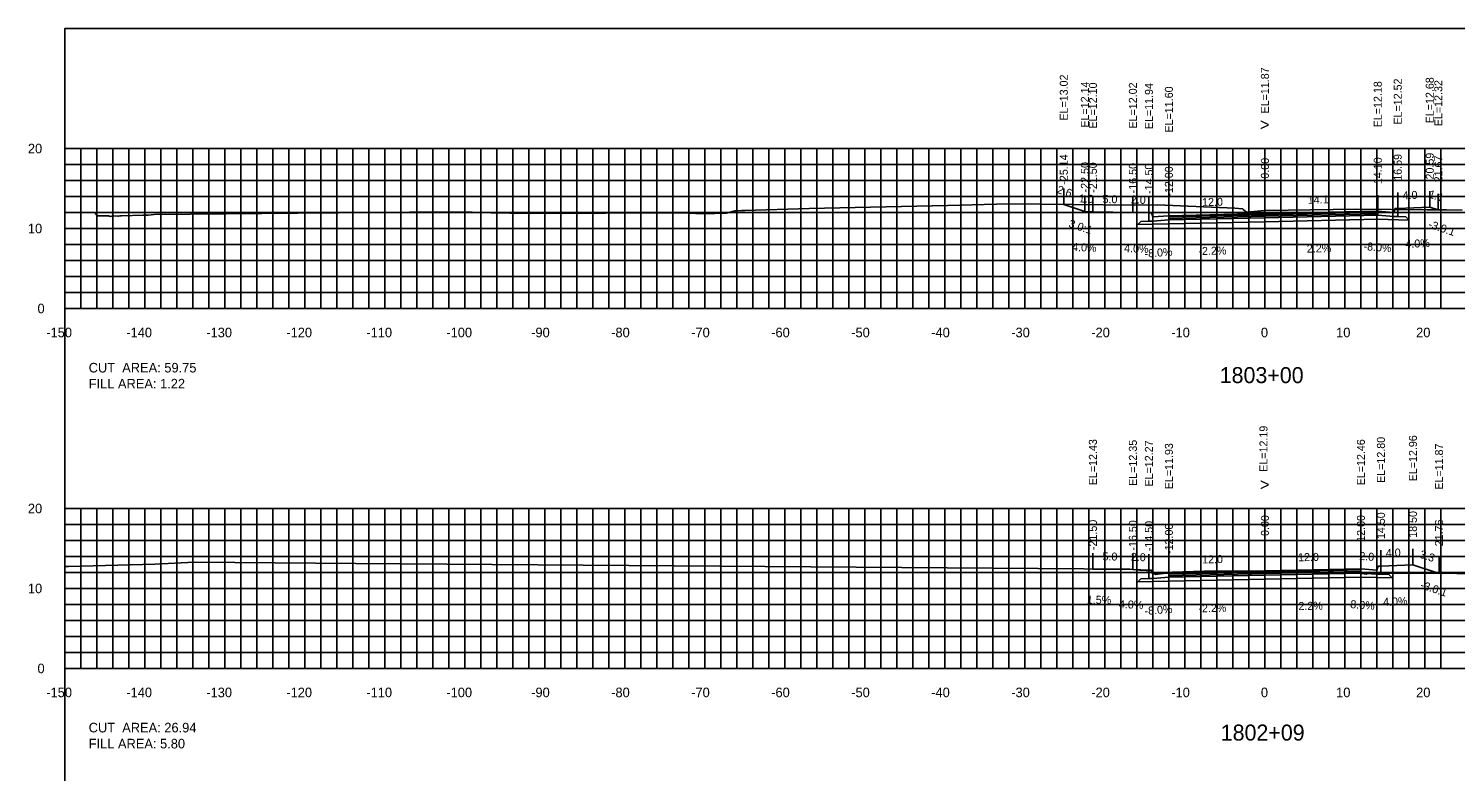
# Model space of a CAD drawing. Extents: x 1797759 to 1802785, y 249826 to 250371.
# Drawn here: x 1802136.5 to 1802314.8, y 250176.5 to 250269.4 of the extents above; entities that cross this region are included whole.
import ezdxf

# ---------------------------------------------------------------- set-up
doc = ezdxf.new("R2010")
doc.units = 0
for name, color, linetype in [('29', 7, 'Continuous'), ('AXIS', 7, 'Continuous'), ('great seal', 7, 'Continuous'), ('Level 1', 7, 'Continuous'), ('Level 10', 7, 'Continuous'), ('Level 13', 7, 'Continuous'), ('Level 15', 7, 'Continuous'), ('Level 30', 7, 'Continuous'), ('Level 40', 7, 'Continuous'), ('Level 45', 7, 'Continuous'), ('Level 63', 7, 'Continuous'), ('Level 7', 7, 'Continuous'), ('LS-SURVEY POINT', 7, 'Continuous'), ('PIPE', 7, 'Continuous'), ('TOPO', 7, 'Continuous')]:
    doc.layers.add(name, color=color, linetype=linetype)

msp = doc.modelspace()

# ---------------------------------------------------------------- linework, layer by layer
at = {"layer": '29'}
for points in [[(1802279, 250245.88), (1802291, 250246.15), (1802305.1, 250246.46), (1802305.1, 250246.27), (1802291, 250245.96), (1802279, 250245.69)], [(1802279, 250201.21), (1802291, 250201.48), (1802303, 250201.74), (1802303, 250201.55), (1802291, 250201.29), (1802279, 250201.02)]]:
    msp.add_lwpolyline(points, close=True, dxfattribs=at)
at = {"layer": 'AXIS'}
for p, q in [((1802265.86, 250247.45), (1802265.86, 250249.45)), ((1802268.5, 250246.57), (1802268.5, 250248.57)), ((1802269.5, 250246.53), (1802269.5, 250248.53)), ((1802274.5, 250246.45), (1802274.5, 250248.45)), ((1802276.5, 250246.37), (1802276.5, 250248.37)), ((1802279, 250246.03), (1802279, 250248.03)), ((1802291, 250246.3), (1802291, 250248.3)), ((1802305.1, 250246.61), (1802305.1, 250248.61)), ((1802307.6, 250246.95), (1802307.6, 250248.95)), ((1802311.6, 250247.11), (1802311.6, 250249.11)), ((1802312.67, 250246.75), (1802312.67, 250248.75)), ((1802269.5, 250201.86), (1802269.5, 250203.86)), ((1802274.5, 250201.78), (1802274.5, 250203.78)), ((1802276.5, 250201.7), (1802276.5, 250203.7)), ((1802279, 250201.36), (1802279, 250203.36)), ((1802291, 250201.63), (1802291, 250203.63)), ((1802303, 250201.89), (1802303, 250203.89)), ((1802305.5, 250202.23), (1802305.5, 250204.23)), ((1802309.5, 250202.39), (1802309.5, 250204.39)), ((1802312.76, 250201.3), (1802312.76, 250203.3))]:
    msp.add_line(p, q, dxfattribs=at)
for points in [[(1802141, 250079.43), (1802441, 250079.43), (1802441, 250269.43), (1802141, 250269.43)], [(1802279, 250246.03), (1802277, 250245.87), (1802276.83, 250246.37), (1802276.5, 250246.37), (1802276.5, 250245.34), (1802277, 250245.34), (1802279, 250245.5)], [(1802305.1, 250246.61), (1802307.1, 250246.45), (1802307.27, 250246.95), (1802307.6, 250246.95), (1802307.6, 250245.92), (1802307.1, 250245.92), (1802305.1, 250246.08)], [(1802279, 250201.36), (1802277, 250201.2), (1802276.83, 250201.7), (1802276.5, 250201.7), (1802276.5, 250200.67), (1802277, 250200.67), (1802279, 250200.83)], [(1802303, 250201.89), (1802305, 250201.73), (1802305.17, 250202.23), (1802305.5, 250202.23), (1802305.5, 250201.2), (1802305, 250201.2), (1802303, 250201.36)]]:
    msp.add_lwpolyline(points, close=True, dxfattribs=at)
at = {"layer": 'great seal'}
for points in [[(1802141, 250246.46), (1802142.96, 250246.44), (1802144.83, 250246.42), (1802144.87, 250246.29), (1802145.01, 250246.1), (1802145.03, 250246.01), (1802145.75, 250246.02), (1802145.86, 250246.02), (1802146.44, 250246.02), (1802146.45, 250246.02), (1802146.48, 250246.02), (1802146.57, 250245.99), (1802146.61, 250245.98), (1802146.73, 250245.95), (1802147, 250246.02), (1802147.02, 250246.02), (1802147.13, 250246.01), (1802147.65, 250245.98), (1802147.72, 250245.99), (1802147.91, 250246.03), (1802148.09, 250246.03), (1802150.82, 250246.08), (1802151.43, 250246.08), (1802152.19, 250246.19), (1802174.65, 250246.39), (1802175.24, 250246.41), (1802184.1, 250246.49), (1802186.87, 250246.47), (1802191.91, 250246.46), (1802191.94, 250246.45), (1802198.98, 250246.29), (1802199.05, 250246.31), (1802218.14, 250246.38), (1802220.77, 250246.28), (1802223.66, 250246.36), (1802224.78, 250246.64), (1802225.62, 250246.67), (1802225.99, 250246.69), (1802234.03, 250246.92), (1802251.33, 250247.32), (1802258.99, 250247.52), (1802274.75, 250247.36), (1802277.54, 250247.39), (1802287.25, 250246.96), (1802288.2, 250246.9), (1802288.3, 250246.79), (1802288.68, 250246.46), (1802289.22, 250246.53), (1802290.9, 250246.68), (1802293.91, 250246.71), (1802302.32, 250246.83), (1802311.28, 250246.75), (1802313.71, 250246.75), (1802315.65, 250246.74)], [(1802141, 250202.16), (1802141.46, 250202.18), (1802152.27, 250202.48), (1802157.21, 250202.7), (1802177.37, 250202.55), (1802274.05, 250201.83), (1802274.1, 250201.83), (1802275.38, 250201.72), (1802276.93, 250201.62), (1802277.09, 250201.44), (1802277.32, 250201.16), (1802278.59, 250201.33), (1802279.41, 250201.45), (1802283.42, 250201.57), (1802290.08, 250201.65), (1802299.57, 250201.38), (1802302.08, 250201.4), (1802302.77, 250201.35), (1802303.71, 250201.23), (1802303.81, 250201.31), (1802304.29, 250201.29), (1802306.24, 250201.28), (1802306.24, 250201.28), (1802307.57, 250201.34), (1802307.6, 250201.33), (1802329.75, 250201.22)]]:
    msp.add_lwpolyline(points, dxfattribs=at)
at = {"layer": 'Level 1'}
for points in [[(1802265.86, 250247.45), (1802268.5, 250246.57), (1802269.5, 250246.53), (1802274.5, 250246.45), (1802276.5, 250246.37), (1802276.83, 250246.37), (1802277, 250245.87), (1802279, 250246.03), (1802291, 250246.3), (1802305.1, 250246.61), (1802307.1, 250246.45), (1802307.27, 250246.95), (1802307.6, 250246.95), (1802311.6, 250247.11), (1802312.67, 250246.75)], [(1802269.5, 250201.86), (1802274.5, 250201.78), (1802276.5, 250201.7), (1802276.83, 250201.7), (1802277, 250201.2), (1802279, 250201.36), (1802291, 250201.63), (1802303, 250201.89), (1802305, 250201.73), (1802305.17, 250202.23), (1802305.5, 250202.23), (1802309.5, 250202.39), (1802312.76, 250201.3)]]:
    msp.add_lwpolyline(points, dxfattribs=at)
at = {"layer": 'Level 13'}
for points in [[(1802305.1, 250245.58), (1802309, 250245.49), (1802308.6, 250245.9), (1802307.6, 250245.92), (1802307.1, 250245.92), (1802305.1, 250246.08), (1802291, 250245.77), (1802279, 250245.5), (1802277, 250245.34), (1802276.5, 250245.34), (1802275.5, 250245.32), (1802275.1, 250244.92), (1802279, 250245), (1802291, 250245.27)], [(1802303, 250200.86), (1802306.9, 250200.77), (1802306.5, 250201.18), (1802305.5, 250201.2), (1802305, 250201.2), (1802303, 250201.36), (1802291, 250201.1), (1802279, 250200.83), (1802277, 250200.67), (1802276.5, 250200.67), (1802275.5, 250200.65), (1802275.1, 250200.25), (1802279, 250200.33), (1802291, 250200.6)]]:
    msp.add_lwpolyline(points, close=True, dxfattribs=at)
at = {"layer": 'Level 15'}
for p, q in [((1802141, 250254.43), (1802441, 250254.43)), ((1802141, 250234.43), (1802141, 250254.43)), ((1802143, 250234.43), (1802143, 250254.43)), ((1802145, 250234.43), (1802145, 250254.43)), ((1802147, 250234.43), (1802147, 250254.43)), ((1802149, 250234.43), (1802149, 250254.43)), ((1802151, 250234.43), (1802151, 250254.43)), ((1802153, 250234.43), (1802153, 250254.43)), ((1802155, 250234.43), (1802155, 250254.43)), ((1802157, 250234.43), (1802157, 250254.43)), ((1802159, 250234.43), (1802159, 250254.43)), ((1802161, 250234.43), (1802161, 250254.43)), ((1802163, 250234.43), (1802163, 250254.43)), ((1802165, 250234.43), (1802165, 250254.43)), ((1802167, 250234.43), (1802167, 250254.43)), ((1802169, 250234.43), (1802169, 250254.43)), ((1802171, 250234.43), (1802171, 250254.43)), ((1802173, 250234.43), (1802173, 250254.43)), ((1802175, 250234.43), (1802175, 250254.43)), ((1802177, 250234.43), (1802177, 250254.43)), ((1802179, 250234.43), (1802179, 250254.43)), ((1802181, 250234.43), (1802181, 250254.43)), ((1802183, 250234.43), (1802183, 250254.43)), ((1802185, 250234.43), (1802185, 250254.43)), ((1802187, 250234.43), (1802187, 250254.43)), ((1802189, 250234.43), (1802189, 250254.43)), ((1802191, 250234.43), (1802191, 250254.43)), ((1802193, 250234.43), (1802193, 250254.43)), ((1802195, 250234.43), (1802195, 250254.43)), ((1802197, 250234.43), (1802197, 250254.43)), ((1802199, 250234.43), (1802199, 250254.43)), ((1802201, 250234.43), (1802201, 250254.43)), ((1802203, 250234.43), (1802203, 250254.43)), ((1802205, 250234.43), (1802205, 250254.43)), ((1802207, 250234.43), (1802207, 250254.43)), ((1802209, 250234.43), (1802209, 250254.43)), ((1802211, 250234.43), (1802211, 250254.43)), ((1802213, 250234.43), (1802213, 250254.43)), ((1802215, 250234.43), (1802215, 250254.43)), ((1802217, 250234.43), (1802217, 250254.43)), ((1802219, 250234.43), (1802219, 250254.43)), ((1802221, 250234.43), (1802221, 250254.43)), ((1802223, 250234.43), (1802223, 250254.43)), ((1802225, 250234.43), (1802225, 250254.43)), ((1802227, 250234.43), (1802227, 250254.43)), ((1802229, 250234.43), (1802229, 250254.43)), ((1802231, 250234.43), (1802231, 250254.43)), ((1802233, 250234.43), (1802233, 250254.43)), ((1802235, 250234.43), (1802235, 250254.43)), ((1802237, 250234.43), (1802237, 250254.43)), ((1802239, 250234.43), (1802239, 250254.43)), ((1802241, 250234.43), (1802241, 250254.43)), ((1802243, 250234.43), (1802243, 250254.43)), ((1802245, 250234.43), (1802245, 250254.43)), ((1802247, 250234.43), (1802247, 250254.43)), ((1802249, 250234.43), (1802249, 250254.43)), ((1802251, 250234.43), (1802251, 250254.43)), ((1802253, 250234.43), (1802253, 250254.43)), ((1802255, 250234.43), (1802255, 250254.43)), ((1802257, 250234.43), (1802257, 250254.43)), ((1802259, 250234.43), (1802259, 250254.43)), ((1802261, 250234.43), (1802261, 250254.43)), ((1802263, 250234.43), (1802263, 250254.43)), ((1802265, 250234.43), (1802265, 250254.43)), ((1802267, 250234.43), (1802267, 250254.43)), ((1802269, 250234.43), (1802269, 250254.43)), ((1802271, 250234.43), (1802271, 250254.43)), ((1802273, 250234.43), (1802273, 250254.43)), ((1802275, 250234.43), (1802275, 250254.43)), ((1802277, 250234.43), (1802277, 250254.43)), ((1802279, 250234.43), (1802279, 250254.43)), ((1802281, 250234.43), (1802281, 250254.43)), ((1802283, 250234.43), (1802283, 250254.43)), ((1802285, 250234.43), (1802285, 250254.43)), ((1802287, 250234.43), (1802287, 250254.43)), ((1802289, 250234.43), (1802289, 250254.43)), ((1802291, 250234.43), (1802291, 250254.43)), ((1802293, 250234.43), (1802293, 250254.43)), ((1802295, 250234.43), (1802295, 250254.43)), ((1802297, 250234.43), (1802297, 250254.43)), ((1802299, 250234.43), (1802299, 250254.43)), ((1802301, 250234.43), (1802301, 250254.43)), ((1802303, 250234.43), (1802303, 250254.43)), ((1802305, 250234.43), (1802305, 250254.43)), ((1802307, 250234.43), (1802307, 250254.43)), ((1802309, 250234.43), (1802309, 250254.43)), ((1802311, 250234.43), (1802311, 250254.43)), ((1802313, 250234.43), (1802313, 250254.43)), ((1802141, 250252.43), (1802441, 250252.43)), ((1802141, 250250.43), (1802441, 250250.43)), ((1802141, 250248.43), (1802441, 250248.43)), ((1802141, 250246.43), (1802441, 250246.43)), ((1802141, 250244.43), (1802441, 250244.43)), ((1802141, 250242.43), (1802441, 250242.43)), ((1802141, 250240.43), (1802441, 250240.43)), ((1802141, 250238.43), (1802441, 250238.43)), ((1802141, 250236.43), (1802441, 250236.43)), ((1802141, 250234.43), (1802441, 250234.43)), ((1802141, 250209.43), (1802441, 250209.43)), ((1802141, 250189.43), (1802141, 250209.43)), ((1802143, 250189.43), (1802143, 250209.43)), ((1802145, 250189.43), (1802145, 250209.43)), ((1802147, 250189.43), (1802147, 250209.43)), ((1802149, 250189.43), (1802149, 250209.43)), ((1802151, 250189.43), (1802151, 250209.43)), ((1802153, 250189.43), (1802153, 250209.43)), ((1802155, 250189.43), (1802155, 250209.43)), ((1802157, 250189.43), (1802157, 250209.43)), ((1802159, 250189.43), (1802159, 250209.43)), ((1802161, 250189.43), (1802161, 250209.43)), ((1802163, 250189.43), (1802163, 250209.43)), ((1802165, 250189.43), (1802165, 250209.43)), ((1802167, 250189.43), (1802167, 250209.43)), ((1802169, 250189.43), (1802169, 250209.43)), ((1802171, 250189.43), (1802171, 250209.43)), ((1802173, 250189.43), (1802173, 250209.43)), ((1802175, 250189.43), (1802175, 250209.43)), ((1802177, 250189.43), (1802177, 250209.43)), ((1802179, 250189.43), (1802179, 250209.43)), ((1802181, 250189.43), (1802181, 250209.43)), ((1802183, 250189.43), (1802183, 250209.43)), ((1802185, 250189.43), (1802185, 250209.43)), ((1802187, 250189.43), (1802187, 250209.43)), ((1802189, 250189.43), (1802189, 250209.43)), ((1802191, 250189.43), (1802191, 250209.43)), ((1802193, 250189.43), (1802193, 250209.43)), ((1802195, 250189.43), (1802195, 250209.43)), ((1802197, 250189.43), (1802197, 250209.43)), ((1802199, 250189.43), (1802199, 250209.43)), ((1802201, 250189.43), (1802201, 250209.43)), ((1802203, 250189.43), (1802203, 250209.43)), ((1802205, 250189.43), (1802205, 250209.43)), ((1802207, 250189.43), (1802207, 250209.43)), ((1802209, 250189.43), (1802209, 250209.43)), ((1802211, 250189.43), (1802211, 250209.43)), ((1802213, 250189.43), (1802213, 250209.43)), ((1802215, 250189.43), (1802215, 250209.43)), ((1802217, 250189.43), (1802217, 250209.43)), ((1802219, 250189.43), (1802219, 250209.43)), ((1802221, 250189.43), (1802221, 250209.43)), ((1802223, 250189.43), (1802223, 250209.43)), ((1802225, 250189.43), (1802225, 250209.43)), ((1802227, 250189.43), (1802227, 250209.43)), ((1802229, 250189.43), (1802229, 250209.43)), ((1802231, 250189.43), (1802231, 250209.43)), ((1802233, 250189.43), (1802233, 250209.43)), ((1802235, 250189.43), (1802235, 250209.43)), ((1802237, 250189.43), (1802237, 250209.43)), ((1802239, 250189.43), (1802239, 250209.43)), ((1802241, 250189.43), (1802241, 250209.43)), ((1802243, 250189.43), (1802243, 250209.43)), ((1802245, 250189.43), (1802245, 250209.43)), ((1802247, 250189.43), (1802247, 250209.43)), ((1802249, 250189.43), (1802249, 250209.43)), ((1802251, 250189.43), (1802251, 250209.43)), ((1802253, 250189.43), (1802253, 250209.43)), ((1802255, 250189.43), (1802255, 250209.43)), ((1802257, 250189.43), (1802257, 250209.43)), ((1802259, 250189.43), (1802259, 250209.43)), ((1802261, 250189.43), (1802261, 250209.43)), ((1802263, 250189.43), (1802263, 250209.43)), ((1802265, 250189.43), (1802265, 250209.43)), ((1802267, 250189.43), (1802267, 250209.43)), ((1802269, 250189.43), (1802269, 250209.43)), ((1802271, 250189.43), (1802271, 250209.43)), ((1802273, 250189.43), (1802273, 250209.43)), ((1802275, 250189.43), (1802275, 250209.43)), ((1802277, 250189.43), (1802277, 250209.43)), ((1802279, 250189.43), (1802279, 250209.43)), ((1802281, 250189.43), (1802281, 250209.43)), ((1802283, 250189.43), (1802283, 250209.43)), ((1802285, 250189.43), (1802285, 250209.43)), ((1802287, 250189.43), (1802287, 250209.43)), ((1802289, 250189.43), (1802289, 250209.43)), ((1802291, 250189.43), (1802291, 250209.43)), ((1802293, 250189.43), (1802293, 250209.43)), ((1802295, 250189.43), (1802295, 250209.43)), ((1802297, 250189.43), (1802297, 250209.43)), ((1802299, 250189.43), (1802299, 250209.43)), ((1802301, 250189.43), (1802301, 250209.43)), ((1802303, 250189.43), (1802303, 250209.43)), ((1802305, 250189.43), (1802305, 250209.43)), ((1802307, 250189.43), (1802307, 250209.43)), ((1802309, 250189.43), (1802309, 250209.43)), ((1802311, 250189.43), (1802311, 250209.43)), ((1802313, 250189.43), (1802313, 250209.43)), ((1802141, 250207.43), (1802441, 250207.43)), ((1802141, 250205.43), (1802441, 250205.43)), ((1802141, 250203.43), (1802441, 250203.43)), ((1802141, 250201.43), (1802441, 250201.43)), ((1802141, 250199.43), (1802441, 250199.43)), ((1802141, 250197.43), (1802441, 250197.43)), ((1802141, 250195.43), (1802441, 250195.43)), ((1802141, 250193.43), (1802441, 250193.43)), ((1802141, 250191.43), (1802441, 250191.43)), ((1802141, 250189.43), (1802441, 250189.43))]:
    msp.add_line(p, q, dxfattribs=at)
at = {"layer": 'Level 30'}
for p, q in [((1802140.94, 250254.43), (1802141, 250254.43)), ((1802141, 250234.43), (1802141, 250254.43)), ((1802140.94, 250244.43), (1802141, 250244.43)), ((1802140.94, 250234.43), (1802141, 250234.43)), ((1802141, 250234.43), (1802441, 250234.43)), ((1802141, 250234.37), (1802141, 250234.43)), ((1802151, 250234.37), (1802151, 250234.43)), ((1802161, 250234.37), (1802161, 250234.43)), ((1802171, 250234.37), (1802171, 250234.43)), ((1802181, 250234.37), (1802181, 250234.43)), ((1802191, 250234.37), (1802191, 250234.43)), ((1802201, 250234.37), (1802201, 250234.43)), ((1802211, 250234.37), (1802211, 250234.43)), ((1802221, 250234.37), (1802221, 250234.43)), ((1802231, 250234.37), (1802231, 250234.43)), ((1802241, 250234.37), (1802241, 250234.43)), ((1802251, 250234.37), (1802251, 250234.43)), ((1802261, 250234.37), (1802261, 250234.43)), ((1802271, 250234.37), (1802271, 250234.43)), ((1802281, 250234.37), (1802281, 250234.43)), ((1802291, 250234.37), (1802291, 250234.43)), ((1802301, 250234.37), (1802301, 250234.43)), ((1802311, 250234.37), (1802311, 250234.43)), ((1802140.94, 250209.43), (1802141, 250209.43)), ((1802141, 250189.43), (1802141, 250209.43)), ((1802140.94, 250199.43), (1802141, 250199.43)), ((1802140.94, 250189.43), (1802141, 250189.43)), ((1802141, 250189.43), (1802441, 250189.43)), ((1802141, 250189.37), (1802141, 250189.43)), ((1802151, 250189.37), (1802151, 250189.43)), ((1802161, 250189.37), (1802161, 250189.43)), ((1802171, 250189.37), (1802171, 250189.43)), ((1802181, 250189.37), (1802181, 250189.43)), ((1802191, 250189.37), (1802191, 250189.43)), ((1802201, 250189.37), (1802201, 250189.43)), ((1802211, 250189.37), (1802211, 250189.43)), ((1802221, 250189.37), (1802221, 250189.43)), ((1802231, 250189.37), (1802231, 250189.43)), ((1802241, 250189.37), (1802241, 250189.43)), ((1802251, 250189.37), (1802251, 250189.43)), ((1802261, 250189.37), (1802261, 250189.43)), ((1802271, 250189.37), (1802271, 250189.43)), ((1802281, 250189.37), (1802281, 250189.43)), ((1802291, 250189.37), (1802291, 250189.43)), ((1802301, 250189.37), (1802301, 250189.43)), ((1802311, 250189.37), (1802311, 250189.43))]:
    msp.add_line(p, q, dxfattribs=at)
at = {"layer": 'PIPE'}
for points in [[(1802279, 250245.5), (1802279, 250245.69), (1802291, 250245.96), (1802305.1, 250246.27), (1802305.1, 250246.08), (1802291, 250245.77)], [(1802279, 250200.83), (1802279, 250201.02), (1802291, 250201.29), (1802303, 250201.55), (1802303, 250201.36), (1802291, 250201.1)]]:
    msp.add_lwpolyline(points, close=True, dxfattribs=at)
at = {"layer": 'TOPO'}
for points in [[(1802305.1, 250246.46), (1802305.1, 250246.61), (1802291, 250246.3), (1802279, 250246.03), (1802279, 250245.88), (1802291, 250246.15)], [(1802303, 250201.74), (1802303, 250201.89), (1802291, 250201.63), (1802279, 250201.36), (1802279, 250201.21), (1802291, 250201.48)]]:
    msp.add_lwpolyline(points, close=True, dxfattribs=at)

# ---------------------------------------------------------------- texts
at = {"layer": 'AXIS'}
for s, p in [('3.0:1', (1802266.39, 250244.64)), ('-3.0:1', (1802311.34, 250244.56)), ('-3.0:1', (1802310.34, 250199.47))]:
    msp.add_text(s, height=1, rotation=341.5651, dxfattribs=at).set_placement(p)
at = {"layer": 'Level 10'}
for s, p in [('1803+00', (1802285.35, 250225.1)), ('1802+09', (1802285.48, 250180.41))]:
    msp.add_text(s, height=2, dxfattribs=at).set_placement(p)
at = {"layer": 'Level 30'}
for s, height, p in [('>', 1.5, (1802290.39, 250256.68)), ('-', 0.0001, (1802141, 250234.43)), ('>', 1.5, (1802290.39, 250211.68)), ('-', 0.0001, (1802141, 250189.43))]:
    msp.add_text(s, height=height, dxfattribs=at).set_placement(p)
at = {"layer": 'Level 40'}
for s, p in [('EL=11.87', (1802291.5, 250258.81)), ('EL=13.02', (1802266.36, 250257.92)), ('EL=12.14', (1802269, 250257.04)), ('EL=12.10', (1802270, 250256.92)), ('EL=12.02', (1802275, 250256.93)), ('EL=11.94', (1802277, 250256.85)), ('EL=11.60', (1802279.5, 250256.43)), ('EL=12.18', (1802305.6, 250257.08)), ('EL=12.52', (1802308.1, 250257.42)), ('EL=12.68', (1802312.1, 250257.58)), ('EL=12.32', (1802313.17, 250257.22)), ('-25.14', (1802266.36, 250249.91)), ('0.00', (1802291.5, 250250.66)), ('14.10', (1802305.6, 250249.98)), ('16.59', (1802308.1, 250250.4)), ('20.59', (1802312.1, 250250.56)), ('21.67', (1802313.17, 250250.2)), ('-22.50', (1802269, 250248.95)), ('-21.50', (1802270, 250248.91)), ('-16.50', (1802275, 250248.83)), ('-14.50', (1802277, 250248.75)), ('-12.00', (1802279.5, 250248.41)), ('EL=12.19', (1802291.32, 250214.01)), ('EL=12.43', (1802270, 250212.33)), ('EL=12.35', (1802275, 250212.25)), ('EL=12.27', (1802277, 250212.17)), ('EL=11.93', (1802279.5, 250211.83)), ('EL=12.46', (1802303.5, 250212.32)), ('EL=12.80', (1802306, 250212.62)), ('EL=12.96', (1802310, 250212.82)), ('EL=11.87', (1802313.26, 250211.78)), ('0.00', (1802291.5, 250205.99)), ('12.00', (1802303.5, 250205.26)), ('14.50', (1802306, 250205.6)), ('18.50', (1802310, 250205.76)), ('-21.50', (1802270, 250204.23)), ('-16.50', (1802275, 250204.16)), ('-14.50', (1802277, 250204.08)), ('-12.00', (1802279.5, 250203.74)), ('21.76', (1802313.26, 250204.7))]:
    msp.add_text(s, height=1, rotation=90, dxfattribs=at).set_placement(p)
at = {"layer": 'Level 45'}
for s, p in [('-150', (1802138.7, 250230.83)), ('-140', (1802148.7, 250230.83)), ('-130', (1802158.7, 250230.83)), ('-120', (1802168.7, 250230.83)), ('-110', (1802178.7, 250230.83)), ('-100', (1802188.7, 250230.83)), ('-90', (1802199.3, 250230.83)), ('-80', (1802209.3, 250230.83)), ('-70', (1802219.3, 250230.83)), ('-60', (1802229.3, 250230.83)), ('-50', (1802239.3, 250230.83)), ('-40', (1802249.3, 250230.83)), ('-30', (1802259.3, 250230.83)), ('-20', (1802269.3, 250230.83)), ('-10', (1802279.3, 250230.83)), ('0', (1802290.5, 250230.83)), ('10', (1802299.9, 250230.83)), ('20', (1802309.9, 250230.83)), ('-150', (1802138.7, 250185.83)), ('-140', (1802148.7, 250185.83)), ('-130', (1802158.7, 250185.83)), ('-120', (1802168.7, 250185.83)), ('-110', (1802178.7, 250185.83)), ('-100', (1802188.7, 250185.83)), ('-90', (1802199.3, 250185.83)), ('-80', (1802209.3, 250185.83)), ('-70', (1802219.3, 250185.83)), ('-60', (1802229.3, 250185.83)), ('-50', (1802239.3, 250185.83)), ('-40', (1802249.3, 250185.83)), ('-30', (1802259.3, 250185.83)), ('-20', (1802269.3, 250185.83)), ('-10', (1802279.3, 250185.83)), ('0', (1802290.5, 250185.83)), ('10', (1802299.9, 250185.83)), ('20', (1802309.9, 250185.83))]:
    msp.add_text(s, height=1.2, dxfattribs=at).set_placement(p)
at = {"layer": 'Level 63'}
for s, rotation, p in [('2.6', 341.5651, (1802264.93, 250248.9)), ('1.0', 357.7094, (1802267.73, 250247.7)), ('5.0', 359.1406, (1802270.7, 250247.61)), ('2.0', 357.7094, (1802274.23, 250247.57)), ('12.0', 1.2603, (1802283.16, 250247.22)), ('14.1', 1.2603, (1802296.37, 250247.52)), ('4.0', 2.2906, (1802308.23, 250248.07)), ('1.1', 341.5651, (1802311.38, 250248.34)), ('4.0%', 357.7094, (1802266.89, 250241.63)), ('4.0%', 357.7094, (1802273.39, 250241.49)), ('2.2%', 1.2603, (1802296.25, 250241.41)), ('-8.0%', 355.4261, (1802303.3, 250241.74)), ('4.0%', 2.2906, (1802308.58, 250242)), ('-8.0%', 4.5739, (1802276, 250240.78)), ('-2.2%', 1.2603, (1802282.7, 250241.11)), ('5.0', 359.1406, (1802270.7, 250202.94)), ('2.0', 357.7094, (1802274.23, 250202.89)), ('12.0', 1.2603, (1802283.16, 250202.55)), ('12.0', 1.2603, (1802295.16, 250202.82)), ('2.0', 355.4261, (1802302.77, 250203.01)), ('4.0', 2.2906, (1802306.13, 250203.36)), ('3.3', 341.5651, (1802310.26, 250203.3)), ('1.5%', 359.1406, (1802268.74, 250197.53)), ('4.0%', 357.7094, (1802272.74, 250196.98)), ('2.2%', 1.2603, (1802295.2, 250196.72)), ('-8.0%', 355.4261, (1802301.2, 250197.02)), ('4.0%', 2.2906, (1802305.79, 250197.24)), ('-8.0%', 4.5739, (1802276, 250196.11)), ('-2.2%', 1.2603, (1802282.7, 250196.44))]:
    msp.add_text(s, height=1, rotation=rotation, dxfattribs=at).set_placement(p)
at = {"layer": 'Level 7'}
for s, p in [('20', (1802136.4, 250253.83)), ('10', (1802136.4, 250243.83)), ('0', (1802137.6, 250233.83)), ('20', (1802136.4, 250208.83)), ('10', (1802136.4, 250198.83)), ('0', (1802137.6, 250188.83))]:
    msp.add_text(s, height=1.2, dxfattribs=at).set_placement(p)
at = {"layer": 'LS-SURVEY POINT'}
for s, p in [('CUT  AREA: 59.75', (1802144, 250226.43)), ('FILL AREA: 1.22', (1802144, 250224.43)), ('CUT  AREA: 26.94', (1802144, 250181.43)), ('FILL AREA: 5.80', (1802144, 250179.43))]:
    msp.add_text(s, height=1.2, dxfattribs=at).set_placement(p)

doc.saveas('drawing.dxf')
